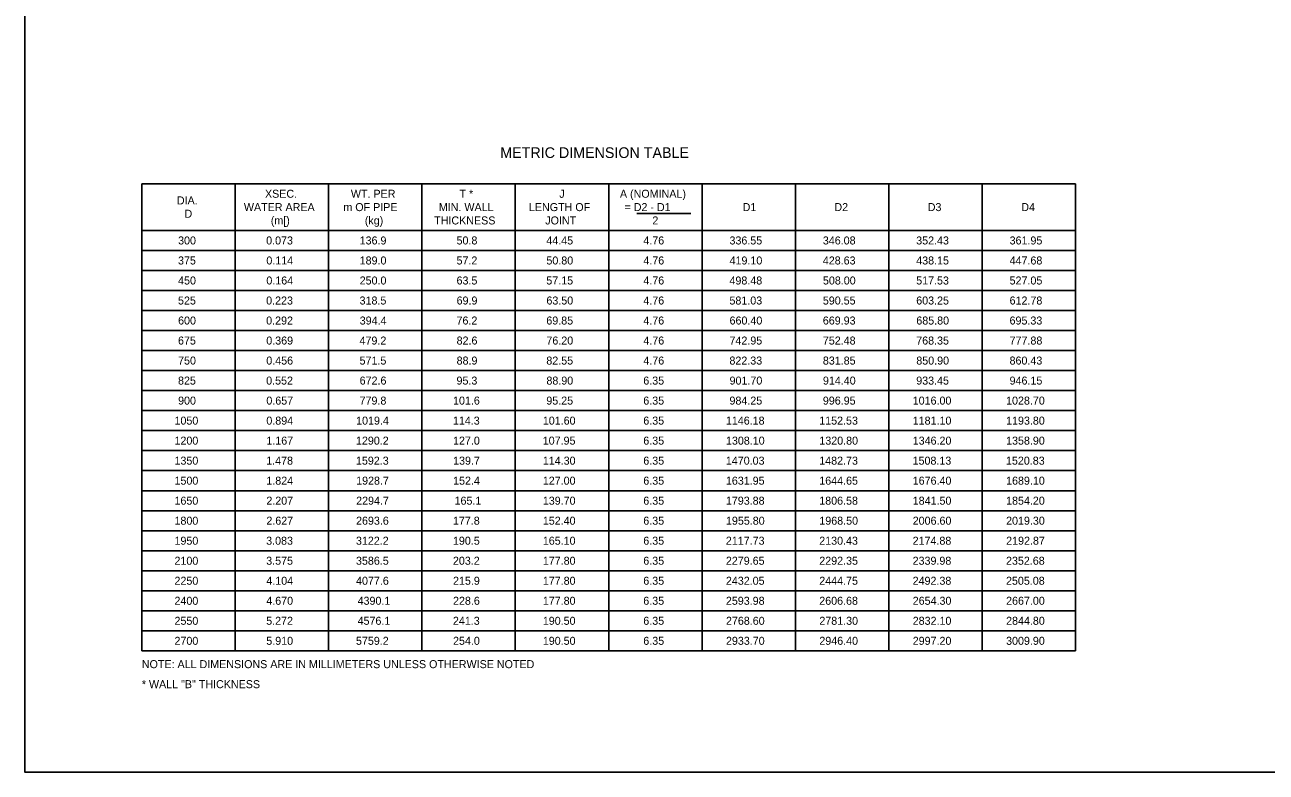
# Model space of a CAD drawing. Extents: x 49991.4 to 50021, y 49987.6 to 50011.4.
# Drawn here: x 49999.38 to 50008.69, y 49987.8 to 49993.4 of the extents above; entities that cross this region are included whole.
import ezdxf

# ---------------------------------------------------------------- set-up
doc = ezdxf.new("R2010")
doc.units = 0
doc.layers.add('Level 1', color=7, linetype='Continuous')
doc.layers.add('Level 2', color=7, linetype='Continuous')

msp = doc.modelspace()

# ---------------------------------------------------------------- linework, layer by layer
at = {"layer": 'Level 1'}
msp.add_lwpolyline([(49999.3835, 49998.9992), (50016.7501, 49998.9992), (50016.7501, 49987.7988), (49999.3835, 49987.7988)], close=True, dxfattribs=at)
at = {"layer": 'Level 2'}
for p, q in [((50000.2607, 49992.2082), (50007.2607, 49992.2082)), ((50000.2607, 49992.2082), (50000.2607, 49988.7082)), ((50000.9607, 49992.2082), (50000.9607, 49988.7082)), ((50001.6607, 49992.2082), (50001.6607, 49988.7082)), ((50002.3607, 49992.2082), (50002.3607, 49988.7082)), ((50003.0607, 49992.2082), (50003.0607, 49988.7082)), ((50003.7607, 49992.2082), (50003.7607, 49988.7082)), ((50004.4607, 49992.2082), (50004.4607, 49988.7082)), ((50005.1607, 49992.2082), (50005.1607, 49988.7082)), ((50005.8607, 49992.2082), (50005.8607, 49988.7082)), ((50006.5607, 49992.2082), (50006.5607, 49988.7082)), ((50007.2607, 49992.2082), (50007.2607, 49988.7082)), ((50003.9714, 49991.9841), (50004.3775, 49991.9841)), ((50000.2607, 49991.8582), (50007.2607, 49991.8582)), ((50000.2607, 49991.7082), (50007.2607, 49991.7082)), ((50000.2607, 49991.5582), (50007.2607, 49991.5582)), ((50000.2607, 49991.4082), (50007.2607, 49991.4082)), ((50000.2607, 49991.2582), (50007.2607, 49991.2582)), ((50000.2607, 49991.1082), (50007.2607, 49991.1082)), ((50000.2607, 49990.9582), (50007.2607, 49990.9582)), ((50000.2607, 49990.8082), (50007.2607, 49990.8082)), ((50000.2607, 49990.6582), (50007.2607, 49990.6582)), ((50000.2607, 49990.5082), (50007.2607, 49990.5082)), ((50000.2607, 49990.3582), (50007.2607, 49990.3582)), ((50000.2607, 49990.2082), (50007.2607, 49990.2082)), ((50000.2607, 49990.0582), (50007.2607, 49990.0582)), ((50000.2607, 49989.9082), (50007.2607, 49989.9082)), ((50000.2607, 49989.7582), (50007.2607, 49989.7582)), ((50000.2607, 49989.6082), (50007.2607, 49989.6082)), ((50000.2607, 49989.4582), (50007.2607, 49989.4582)), ((50000.2607, 49989.3082), (50007.2607, 49989.3082)), ((50000.2607, 49989.1582), (50007.2607, 49989.1582)), ((50000.2607, 49989.0082), (50007.2607, 49989.0082)), ((50000.2607, 49988.8582), (50007.2607, 49988.8582)), ((50000.2607, 49988.7082), (50007.2607, 49988.7082))]:
    msp.add_line(p, q, dxfattribs=at)

# ---------------------------------------------------------------- texts
for s, height, p in [('METRIC DIMENSION TABLE', 0.08, (50002.9479, 49992.4013)), ('DIA.', 0.06, (50000.5234, 49992.0532)), ('XSEC.', 0.06, (50001.184, 49992.1032)), ('WT. PER', 0.06, (50001.8278, 49992.1032)), ('T *', 0.06, (50002.6424, 49992.1032)), ('J', 0.06, (50003.3903, 49992.1032)), (' A (NOMINAL)', 0.06, (50003.8227, 49992.1032)), ('D', 0.06, (50000.5804, 49991.9532)), ('WATER AREA', 0.06, (50001.0257, 49992.0032)), ('m OF PIPE', 0.06, (50001.7717, 49992.0032)), ('MIN. WALL', 0.06, (50002.4873, 49992.0032)), ('LENGTH OF', 0.06, (50003.1627, 49992.0032)), ('= D2 - D1', 0.06, (50003.8793, 49992.0032)), ('D1', 0.06, (50004.7648, 49992.0032)), ('D2', 0.06, (50005.4526, 49992.0032)), ('D3', 0.06, (50006.1525, 49992.0032)), ('D4', 0.06, (50006.8538, 49992.0032)), ('(m[)', 0.06, (50001.2275, 49991.9032)), ('(kg)', 0.06, (50001.9323, 49991.9032)), ('THICKNESS', 0.06, (50002.4522, 49991.9032)), ('JOINT', 0.06, (50003.2852, 49991.9032)), ('  2 ', 0.06, (50004.0435, 49991.9032)), ('300', 0.06, (50000.5325, 49991.7532)), ('0.073', 0.06, (50001.1928, 49991.7532)), ('136.9', 0.06, (50001.8936, 49991.7532)), ('50.8', 0.06, (50002.62, 49991.7532)), ('44.45', 0.06, (50003.2931, 49991.7532)), ('4.76', 0.06, (50004.0205, 49991.7532)), ('336.55', 0.06, (50004.6662, 49991.7532)), ('346.08', 0.06, (50005.3661, 49991.7532)), ('352.43', 0.06, (50006.0659, 49991.7532)), ('361.95', 0.06, (50006.7662, 49991.7532)), ('375', 0.06, (50000.5319, 49991.6032)), ('0.114', 0.06, (50001.1941, 49991.6032)), ('189.0', 0.06, (50001.8937, 49991.6032)), ('57.2', 0.06, (50002.6198, 49991.6032)), ('50.80', 0.06, (50003.2937, 49991.6032)), ('4.76', 0.06, (50004.0205, 49991.6032)), ('419.10', 0.06, (50004.6668, 49991.6032)), ('428.63', 0.06, (50005.3659, 49991.6032)), ('438.15', 0.06, (50006.0662, 49991.6032)), ('447.68', 0.06, (50006.7661, 49991.6032)), ('450', 0.06, (50000.5325, 49991.4532)), ('0.164', 0.06, (50001.1941, 49991.4532)), ('250.0', 0.06, (50001.8937, 49991.4532)), ('63.5', 0.06, (50002.6201, 49991.4532)), ('57.15', 0.06, (50003.2931, 49991.4532)), ('4.76', 0.06, (50004.0205, 49991.4532)), ('498.48', 0.06, (50004.6661, 49991.4532)), ('508.00', 0.06, (50005.3668, 49991.4532)), ('517.53', 0.06, (50006.0659, 49991.4532)), ('527.05', 0.06, (50006.7662, 49991.4532)), ('525', 0.06, (50000.5319, 49991.3032)), ('0.223', 0.06, (50001.1928, 49991.3032)), ('318.5', 0.06, (50001.8931, 49991.3032)), ('69.9', 0.06, (50002.6205, 49991.3032)), ('63.50', 0.06, (50003.2937, 49991.3032)), ('4.76', 0.06, (50004.0205, 49991.3032)), ('581.03', 0.06, (50004.6659, 49991.3032)), ('590.55', 0.06, (50005.3662, 49991.3032)), ('603.25', 0.06, (50006.0662, 49991.3032)), ('612.78', 0.06, (50006.7661, 49991.3032)), ('600', 0.06, (50000.5325, 49991.1532)), ('0.292', 0.06, (50001.1929, 49991.1532)), ('394.4', 0.06, (50001.8941, 49991.1532)), ('76.2', 0.06, (50002.6198, 49991.1532)), ('69.85', 0.06, (50003.2931, 49991.1532)), ('4.76', 0.06, (50004.0205, 49991.1532)), ('660.40', 0.06, (50004.6668, 49991.1532)), ('669.93', 0.06, (50005.3659, 49991.1532)), ('685.80', 0.06, (50006.0668, 49991.1532)), ('695.33', 0.06, (50006.7659, 49991.1532)), ('675', 0.06, (50000.5319, 49991.0032)), ('0.369', 0.06, (50001.1936, 49991.0032)), ('479.2', 0.06, (50001.8929, 49991.0032)), ('82.6', 0.06, (50002.6205, 49991.0032)), ('76.20', 0.06, (50003.2937, 49991.0032)), ('4.76', 0.06, (50004.0205, 49991.0032)), ('742.95', 0.06, (50004.6662, 49991.0032)), ('752.48', 0.06, (50005.3661, 49991.0032)), ('768.35', 0.06, (50006.0662, 49991.0032)), ('777.88', 0.06, (50006.7661, 49991.0032)), ('750', 0.06, (50000.5325, 49990.8532)), ('0.456', 0.06, (50001.1936, 49990.8532)), ('571.5', 0.06, (50001.8931, 49990.8532)), ('88.9', 0.06, (50002.6205, 49990.8532)), ('82.55', 0.06, (50003.2931, 49990.8532)), ('4.76', 0.06, (50004.0205, 49990.8532)), ('822.33', 0.06, (50004.6659, 49990.8532)), ('831.85', 0.06, (50005.3662, 49990.8532)), ('850.90', 0.06, (50006.0668, 49990.8532)), ('860.43', 0.06, (50006.7659, 49990.8532)), ('825', 0.06, (50000.5319, 49990.7032)), ('0.552', 0.06, (50001.1929, 49990.7032)), ('672.6', 0.06, (50001.8936, 49990.7032)), ('95.3', 0.06, (50002.6198, 49990.7032)), ('88.90', 0.06, (50003.2937, 49990.7032)), ('6.35', 0.06, (50004.0201, 49990.7032)), ('901.70', 0.06, (50004.6668, 49990.7032)), ('914.40', 0.06, (50005.3668, 49990.7032)), ('933.45', 0.06, (50006.0662, 49990.7032)), ('946.15', 0.06, (50006.7662, 49990.7032)), ('900', 0.06, (50000.5325, 49990.5532)), ('0.657', 0.06, (50001.1942, 49990.5532)), ('779.8', 0.06, (50001.8931, 49990.5532)), ('101.6', 0.06, (50002.5936, 49990.5532)), ('95.25', 0.06, (50003.2931, 49990.5532)), ('6.35', 0.06, (50004.0201, 49990.5532)), ('984.25', 0.06, (50004.6662, 49990.5532)), ('996.95', 0.06, (50005.3662, 49990.5532)), ('1016.00', 0.06, (50006.0398, 49990.5532)), ('1028.70', 0.06, (50006.7398, 49990.5532)), ('1050', 0.06, (50000.5055, 49990.4032)), ('0.894', 0.06, (50001.1941, 49990.4032)), ('1019.4', 0.06, (50001.8671, 49990.4032)), ('114.3', 0.06, (50002.5928, 49990.4032)), ('101.60', 0.06, (50003.2668, 49990.4032)), ('6.35', 0.06, (50004.0201, 49990.4032)), ('1146.18', 0.06, (50004.6392, 49990.4032)), ('1152.53', 0.06, (50005.339, 49990.4032)), ('1181.10', 0.06, (50006.0398, 49990.4032)), ('1193.80', 0.06, (50006.7398, 49990.4032)), ('1200', 0.06, (50000.5055, 49990.2532)), ('1.167', 0.06, (50001.1942, 49990.2532)), ('1290.2', 0.06, (50001.866, 49990.2532)), ('127.0', 0.06, (50002.5937, 49990.2532)), ('107.95', 0.06, (50003.2662, 49990.2532)), ('6.35', 0.06, (50004.0201, 49990.2532)), ('1308.10', 0.06, (50004.6398, 49990.2532)), ('1320.80', 0.06, (50005.3398, 49990.2532)), ('1346.20', 0.06, (50006.0398, 49990.2532)), ('1358.90', 0.06, (50006.7398, 49990.2532)), ('1350', 0.06, (50000.5055, 49990.1032)), ('1.478', 0.06, (50001.1931, 49990.1032)), ('1592.3', 0.06, (50001.8659, 49990.1032)), ('139.7', 0.06, (50002.5942, 49990.1032)), ('114.30', 0.06, (50003.2668, 49990.1032)), ('6.35', 0.06, (50004.0201, 49990.1032)), ('1470.03', 0.06, (50004.639, 49990.1032)), ('1482.73', 0.06, (50005.339, 49990.1032)), ('1508.13', 0.06, (50006.039, 49990.1032)), ('1520.83', 0.06, (50006.739, 49990.1032)), ('1500', 0.06, (50000.5055, 49989.9532)), ('1.824', 0.06, (50001.1941, 49989.9532)), ('1928.7', 0.06, (50001.8673, 49989.9532)), ('152.4', 0.06, (50002.5941, 49989.9532)), ('127.00', 0.06, (50003.2668, 49989.9532)), ('6.35', 0.06, (50004.0201, 49989.9532)), ('1631.95', 0.06, (50004.6393, 49989.9532)), ('1644.65', 0.06, (50005.3393, 49989.9532)), ('1676.40', 0.06, (50006.0398, 49989.9532)), ('1689.10', 0.06, (50006.7398, 49989.9532)), ('1650', 0.06, (50000.5055, 49989.8032)), ('2.207', 0.06, (50001.1942, 49989.8032)), ('2294.7', 0.06, (50001.8673, 49989.8032)), ('165.1', 0.06, (50002.6051, 49989.8032)), ('139.70', 0.06, (50003.2668, 49989.8032)), ('6.35', 0.06, (50004.0201, 49989.8032)), ('1793.88', 0.06, (50004.6392, 49989.8032)), ('1806.58', 0.06, (50005.3392, 49989.8032)), ('1841.50', 0.06, (50006.0398, 49989.8032)), ('1854.20', 0.06, (50006.7398, 49989.8032)), ('1800', 0.06, (50000.5055, 49989.6532)), ('2.627', 0.06, (50001.1942, 49989.6532)), ('2693.6', 0.06, (50001.8666, 49989.6532)), ('177.8', 0.06, (50002.5931, 49989.6532)), ('152.40', 0.06, (50003.2668, 49989.6532)), ('6.35', 0.06, (50004.0201, 49989.6532)), ('1955.80', 0.06, (50004.6398, 49989.6532)), ('1968.50', 0.06, (50005.3398, 49989.6532)), ('2006.60', 0.06, (50006.0398, 49989.6532)), ('2019.30', 0.06, (50006.7398, 49989.6532)), ('1950', 0.06, (50000.5055, 49989.5032)), ('3.083', 0.06, (50001.1928, 49989.5032)), ('3122.2', 0.06, (50001.866, 49989.5032)), ('190.5', 0.06, (50002.5931, 49989.5032)), ('165.10', 0.06, (50003.2668, 49989.5032)), ('6.35', 0.06, (50004.0201, 49989.5032)), ('2117.73', 0.06, (50004.639, 49989.5032)), ('2130.43', 0.06, (50005.339, 49989.5032)), ('2174.88', 0.06, (50006.0392, 49989.5032)), ('2192.87', 0.06, (50006.7404, 49989.5032)), ('2100', 0.06, (50000.5055, 49989.3532)), ('3.575', 0.06, (50001.1931, 49989.3532)), ('3586.5', 0.06, (50001.8662, 49989.3532)), ('203.2', 0.06, (50002.5929, 49989.3532)), ('177.80', 0.06, (50003.2668, 49989.3532)), ('6.35', 0.06, (50004.0201, 49989.3532)), ('2279.65', 0.06, (50004.6393, 49989.3532)), ('2292.35', 0.06, (50005.3393, 49989.3532)), ('2339.98', 0.06, (50006.0392, 49989.3532)), ('2352.68', 0.06, (50006.7392, 49989.3532)), ('2250', 0.06, (50000.5055, 49989.2032)), ('4.104', 0.06, (50001.1941, 49989.2032)), ('4077.6', 0.06, (50001.8666, 49989.2032)), ('215.9', 0.06, (50002.5936, 49989.2032)), ('177.80', 0.06, (50003.2668, 49989.2032)), ('6.35', 0.06, (50004.0201, 49989.2032)), ('2432.05', 0.06, (50004.6393, 49989.2032)), ('2444.75', 0.06, (50005.3393, 49989.2032)), ('2492.38', 0.06, (50006.0392, 49989.2032)), ('2505.08', 0.06, (50006.7392, 49989.2032)), ('2400', 0.06, (50000.5055, 49989.0532)), ('4.670', 0.06, (50001.1937, 49989.0532)), ('4390.1', 0.06, (50001.8782, 49989.0532)), ('228.6', 0.06, (50002.5936, 49989.0532)), ('177.80', 0.06, (50003.2668, 49989.0532)), ('6.35', 0.06, (50004.0201, 49989.0532)), ('2593.98', 0.06, (50004.6392, 49989.0532)), ('2606.68', 0.06, (50005.3392, 49989.0532)), ('2654.30', 0.06, (50006.0398, 49989.0532)), ('2667.00', 0.06, (50006.7398, 49989.0532)), ('2550', 0.06, (50000.5055, 49988.9032)), ('5.272', 0.06, (50001.1929, 49988.9032)), ('4576.1', 0.06, (50001.8782, 49988.9032)), ('241.3', 0.06, (50002.5928, 49988.9032)), ('190.50', 0.06, (50003.2668, 49988.9032)), ('6.35', 0.06, (50004.0201, 49988.9032)), ('2768.60', 0.06, (50004.6398, 49988.9032)), ('2781.30', 0.06, (50005.3398, 49988.9032)), ('2832.10', 0.06, (50006.0398, 49988.9032)), ('2844.80', 0.06, (50006.7398, 49988.9032)), ('2700', 0.06, (50000.5055, 49988.7532)), ('5.910', 0.06, (50001.1937, 49988.7532)), ('5759.2', 0.06, (50001.866, 49988.7532)), ('254.0', 0.06, (50002.5937, 49988.7532)), ('190.50', 0.06, (50003.2668, 49988.7532)), ('6.35', 0.06, (50004.0201, 49988.7532)), ('2933.70', 0.06, (50004.6398, 49988.7532)), ('2946.40', 0.06, (50005.3398, 49988.7532)), ('2997.20', 0.06, (50006.0398, 49988.7532)), ('3009.90', 0.06, (50006.7398, 49988.7532)), ('NOTE: ALL DIMENSIONS ARE IN MILLIMETERS UNLESS OTHERWISE NOTED', 0.06, (50000.2607, 49988.5782)), ('* WALL "B" THICKNESS', 0.06, (50000.2607, 49988.4282))]:
    msp.add_text(s, height=height, dxfattribs=at).set_placement(p)

doc.saveas('drawing.dxf')
